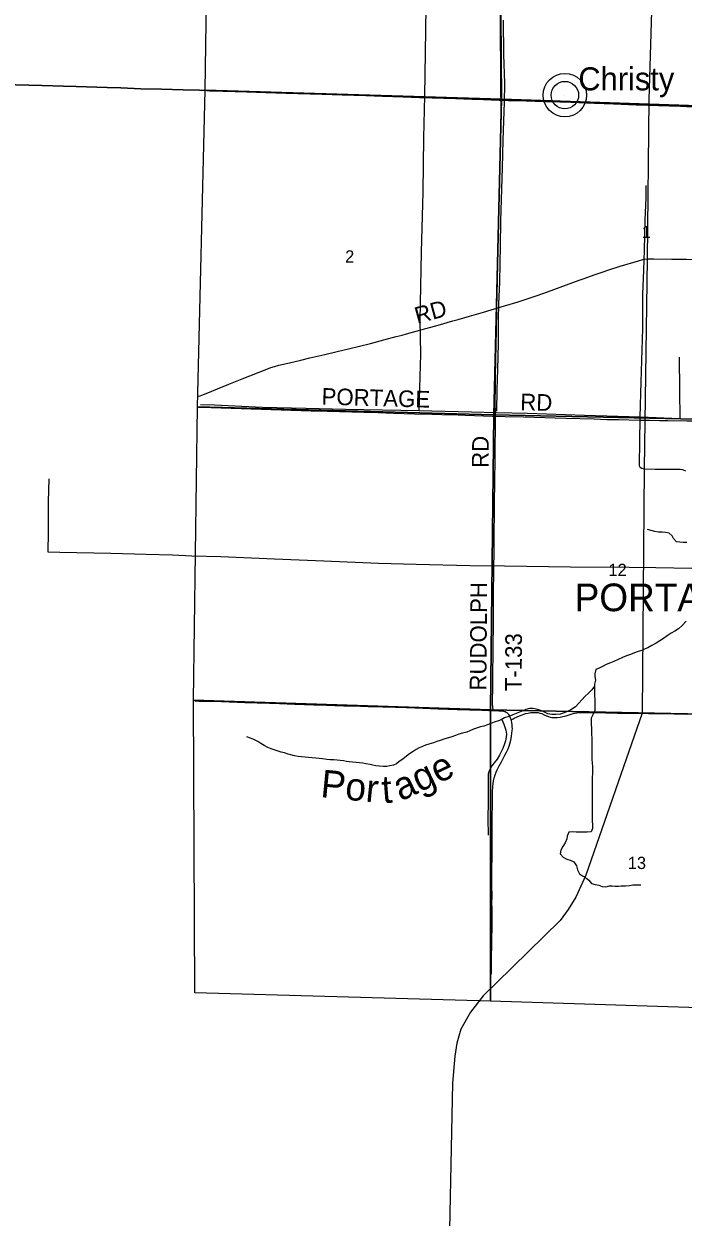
# Model space of a CAD drawing. Extents: x -107 to 120, y -81 to 213.
# Drawn here: x -88.31 to -76.39, y -41 to -19.43 of the extents above; entities that cross this region are included whole.
import ezdxf

# ---------------------------------------------------------------- set-up
doc = ezdxf.new("R2010")
doc.units = 0
for name, color, linetype in [('GM_X_Corporation_Text', 7, 'Continuous'), ('GM_X_Major_River', 7, 'Continuous'), ('GM_X_Major_River_Text', 7, 'Continuous'), ('GM_X_Minor_River', 7, 'Continuous'), ('GM_X_Rail_Line', 7, 'Continuous'), ('GM_X_Section', 7, 'Continuous'), ('GM_X_Section_Text', 7, 'Continuous'), ('GM_X_Township', 7, 'Continuous'), ('GM_X_Township_Road', 7, 'Continuous'), ('GM_X_Township_Road_Text', 7, 'Continuous'), ('GM_X_Unincorporated', 7, 'Continuous'), ('GM_X_Unincorporated_Location', 7, 'Continuous'), ('GM_X_Unincorporated_Text', 7, 'Continuous')]:
    doc.layers.add(name, color=color, linetype=linetype)

msp = doc.modelspace()

# ---------------------------------------------------------------- linework, layer by layer
at = {"layer": 'GM_X_Major_River'}
for points in [[(-76.335, -30.225), (-76.405, -30.307), (-76.474, -30.369), (-76.538, -30.407), (-76.604, -30.447), (-76.676, -30.491), (-76.745, -30.539), (-76.809, -30.583), (-76.875, -30.623), (-76.955, -30.669), (-77.028, -30.707), (-77.078, -30.726), (-77.134, -30.758), (-77.204, -30.778), (-77.27, -30.802), (-77.343, -30.83), (-77.415, -30.854), (-77.485, -30.882), (-77.567, -30.92), (-77.641, -30.955), (-77.704, -30.981), (-77.782, -31.013), (-77.834, -31.039), (-77.898, -31.069)], [(-77.898, -31.069), (-77.966, -31.103), (-77.985, -31.177), (-77.985, -31.227), (-77.975, -31.297), (-77.991, -31.365), (-77.991, -31.402)], [(-77.991, -31.402), (-78.038, -31.47), (-78.108, -31.538), (-78.158, -31.586), (-78.219, -31.648), (-78.273, -31.712), (-78.337, -31.776), (-78.403, -31.821), (-78.468, -31.857), (-78.538, -31.883), (-78.612, -31.909), (-78.692, -31.917), (-78.766, -31.917), (-78.838, -31.904), (-78.906, -31.868), (-78.978, -31.834), (-79.046, -31.816), (-79.099, -31.809), (-79.167, -31.809), (-79.235, -31.825), (-79.289, -31.847), (-79.345, -31.873), (-79.407, -31.897), (-79.468, -31.921), (-79.54, -31.952), (-79.616, -31.978), (-79.68, -32.012), (-79.73, -32.03), (-79.807, -32.054), (-79.863, -32.076), (-79.927, -32.1), (-79.991, -32.124), (-80.053, -32.137), (-80.127, -32.161), (-80.178, -32.181), (-80.244, -32.211), (-80.302, -32.233), (-80.38, -32.255), (-80.446, -32.273), (-80.502, -32.293), (-80.571, -32.316), (-80.631, -32.336), (-80.699, -32.356), (-80.783, -32.388), (-80.841, -32.404), (-80.901, -32.43), (-80.984, -32.454), (-81.046, -32.471), (-81.1, -32.491), (-81.162, -32.519), (-81.214, -32.545), (-81.269, -32.583), (-81.335, -32.629), (-81.389, -32.667), (-81.459, -32.725), (-81.52, -32.767), (-81.572, -32.809), (-81.624, -32.829), (-81.69, -32.846), (-81.748, -32.854), (-81.808, -32.854), (-81.878, -32.848), (-81.946, -32.842), (-81.997, -32.834), (-82.049, -32.821), (-82.123, -32.805), (-82.177, -32.797), (-82.241, -32.789), (-82.297, -32.781), (-82.369, -32.776), (-82.425, -32.772), (-82.475, -32.764), (-82.529, -32.752), (-82.587, -32.744), (-82.643, -32.739), (-82.705, -32.737), (-82.77, -32.735), (-82.832, -32.727), (-82.906, -32.717), (-82.968, -32.708), (-83.03, -32.704), (-83.098, -32.698), (-83.164, -32.692), (-83.22, -32.688), (-83.288, -32.681), (-83.346, -32.675), (-83.416, -32.665), (-83.478, -32.647), (-83.53, -32.63), (-83.596, -32.61), (-83.654, -32.599), (-83.707, -32.58), (-83.763, -32.558), (-83.835, -32.535), (-83.897, -32.511), (-83.965, -32.473), (-84.021, -32.438), (-84.077, -32.406), (-84.149, -32.37), (-84.207, -32.344), (-84.275, -32.321)]]:
    msp.add_lwpolyline(points, dxfattribs=at)
at = {"layer": 'GM_X_Minor_River'}
for points in [[(-81.159, -26.425), (-81.132, -25.4), (-81.14, -24.782), (-81.116, -23.555), (-81.089, -22.464), (-81.074, -21.487), (-81.06, -20.727), (-81.047, -19.954), (-81.035, -19.128), (-81.018, -18.394), (-81.006, -17.654), (-80.999, -17.221), (-81.008, -16.819), (-81.009, -16.529), (-81.002, -16.198), (-81.001, -15.877)], [(-79.645, -19.361), (-79.637, -19.979), (-79.62, -20.502), (-79.625, -20.847), (-79.639, -21.182), (-79.646, -21.531), (-79.659, -22.029), (-79.679, -22.606), (-79.688, -22.993), (-79.697, -23.433), (-79.704, -23.763), (-79.711, -24.098), (-79.725, -24.487), (-79.736, -24.776), (-79.735, -25.209), (-79.748, -25.679), (-79.756, -26.036), (-79.763, -26.433)], [(-76.442, -27.488), (-76.895, -27.484), (-77.088, -27.478), (-77.134, -27.47), (-77.164, -27.447), (-77.178, -27.425), (-77.181, -27.387), (-77.172, -26.988), (-77.169, -26.541), (-77.147, -25.903), (-77.12, -24.938), (-77.116, -24.319), (-77.098, -23.882), (-77.085, -23.521), (-77.074, -22.975), (-77.056, -22.572), (-77.056, -22.347)], [(-76.46, -25.456), (-76.454, -26.052), (-76.448, -26.569), (-77.169, -26.541), (-78.174, -26.506), (-79.202, -26.475), (-79.765, -26.463), (-80.218, -26.447), (-80.935, -26.431), (-81.159, -26.425), (-82.495, -26.402), (-83.212, -26.382), (-83.992, -26.364), (-84.863, -26.319), (-85.113, -26.318)], [(-76.342, -27.516), (-76.393, -27.491), (-76.442, -27.488)], [(-87.858, -27.654), (-87.865, -28.071), (-87.865, -28.619), (-87.872, -28.974), (-87.654, -28.978), (-86.732, -28.995), (-86.095, -29.015), (-85.617, -29.028), (-85.272, -29.045), (-84.749, -29.057), (-83.776, -29.1), (-82.886, -29.135), (-81.897, -29.176), (-81.218, -29.198), (-80.246, -29.221), (-79.621, -29.229), (-78.425, -29.248), (-77.366, -29.254), (-76.881, -29.259), (-76.234, -29.269), (-75.901, -29.28), (-75.604, -29.287)], [(-76.322, -28.804), (-76.391, -28.805), (-76.447, -28.801), (-76.511, -28.791), (-76.561, -28.735), (-76.586, -28.684), (-76.64, -28.636), (-76.708, -28.622), (-76.771, -28.618), (-76.837, -28.618), (-76.901, -28.605), (-76.965, -28.587), (-77.033, -28.567)], [(-77.991, -31.402), (-77.994, -31.506), (-77.992, -31.57), (-77.988, -31.644), (-77.988, -31.704), (-77.987, -31.773), (-77.983, -31.841), (-78.013, -31.909), (-78.051, -31.979), (-78.052, -32.045), (-78.05, -32.097), (-78.048, -32.165), (-78.046, -32.216), (-78.046, -32.268), (-78.041, -32.342), (-78.039, -32.408), (-78.039, -32.544), (-78.039, -32.609), (-78.042, -32.675), (-78.04, -32.725), (-78.036, -32.793), (-78.03, -32.857), (-78.028, -32.926), (-78.029, -32.992), (-78.033, -33.044), (-78.035, -33.102), (-78.035, -33.172), (-78.033, -33.244), (-78.036, -33.315), (-78.034, -33.383), (-78.034, -33.511), (-78.032, -33.577), (-78.031, -33.651), (-78.033, -33.706), (-78.031, -33.772), (-78.031, -33.848), (-78.029, -33.902), (-78.028, -33.974), (-78.05, -34.034), (-78.122, -34.04), (-78.192, -34.042), (-78.258, -34.042), (-78.322, -34.04), (-78.384, -34.038), (-78.455, -34.043), (-78.483, -34.115), (-78.493, -34.166), (-78.521, -34.238), (-78.566, -34.304), (-78.598, -34.37), (-78.61, -34.432), (-78.56, -34.494), (-78.49, -34.529), (-78.43, -34.547), (-78.366, -34.581), (-78.32, -34.653), (-78.3, -34.724), (-78.263, -34.796), (-78.209, -34.834), (-78.155, -34.862), (-78.095, -34.909), (-78.043, -34.971), (-77.977, -34.987), (-77.915, -35), (-77.851, -35.028), (-77.785, -35.034), (-77.722, -35.012), (-77.67, -35.016), (-77.616, -35.018), (-77.56, -35.019), (-77.51, -35.015), (-77.432, -35.011), (-77.358, -35.005), (-77.3, -34.995), (-77.21, -34.994), (-77.153, -34.996)], [(-79.665, -32.004), (-79.628, -32.087), (-79.597, -32.199), (-79.585, -32.269), (-79.589, -32.327), (-79.599, -32.391), (-79.617, -32.446), (-79.648, -32.528), (-79.686, -32.602), (-79.71, -32.648), (-79.753, -32.722), (-79.803, -32.788), (-79.845, -32.844), (-79.895, -32.932), (-79.914, -32.996), (-79.912, -33.179), (-79.913, -33.5), (-79.918, -33.798), (-79.911, -34.097)]]:
    msp.add_lwpolyline(points, dxfattribs=at)
at = {"layer": 'GM_X_Rail_Line'}
msp.add_lwpolyline([(-76.938, -18.389), (-77.01, -20.802), (-77.04, -23.683), (-77.093, -27.462), (-77.13, -31.891), (-78.149, -34.821), (-78.332, -35.218), (-78.47, -35.439), (-78.614, -35.638), (-79.766, -36.764), (-80.006, -37.004), (-80.231, -37.298), (-80.406, -37.602), (-80.479, -37.86), (-80.516, -38.09), (-80.556, -38.584), (-80.636, -42.405)], dxfattribs=at)
at = {"layer": 'GM_X_Section'}
for points in [[(-84.948, -15.325), (-79.714, -15.483), (-79.671, -20.786), (-85.027, -20.624)], [(-79.714, -15.483), (-74.3, -15.65), (-74.292, -15.724), (-74.333, -20.972), (-79.671, -20.786)], [(-85.027, -20.624), (-79.671, -20.786), (-79.814, -26.495), (-85.166, -26.35)], [(-79.671, -20.786), (-74.333, -20.972), (-74.457, -26.613), (-79.814, -26.495)], [(-85.166, -26.35), (-79.814, -26.495), (-79.874, -31.832), (-85.243, -31.655)], [(-79.814, -26.495), (-74.457, -26.613), (-74.459, -26.879), (-74.531, -31.942), (-79.874, -31.832)], [(-85.243, -31.655), (-79.874, -31.832), (-79.873, -37.1), (-85.219, -36.95)], [(-79.874, -31.832), (-74.531, -31.942), (-74.528, -32.154), (-74.587, -37.265), (-79.873, -37.1)]]:
    msp.add_lwpolyline(points, close=True, dxfattribs=at)
at = {"layer": 'GM_X_Township'}
for points in [[(-88.687, -20.521), (-87.982, -20.542), (-87.588, -20.554), (-87.359, -20.561), (-86.801, -20.579), (-86.555, -20.587), (-86.195, -20.6), (-85.818, -20.61), (-85.424, -20.62), (-85.129, -20.628), (-85.002, -20.632), (-84.949, -20.634), (-84.703, -20.643), (-84.276, -20.656), (-83.932, -20.666), (-83.571, -20.677), (-82.915, -20.696), (-82.554, -20.708), (-82.127, -20.722), (-81.832, -20.731), (-81.455, -20.743), (-81.16, -20.753), (-80.931, -20.761), (-80.504, -20.775), (-80.209, -20.785), (-79.996, -20.792), (-79.717, -20.803), (-79.681, -20.804), (-79.553, -20.808), (-79.225, -20.819), (-78.913, -20.828), (-78.618, -20.836), (-78.421, -20.843), (-77.995, -20.858), (-77.651, -20.871), (-77.241, -20.886), (-77.028, -20.895), (-76.832, -20.901), (-76.438, -20.914), (-76.209, -20.922)], [(-76.209, -20.922), (-76.438, -20.914), (-76.832, -20.901), (-77.028, -20.895), (-77.241, -20.886), (-77.651, -20.871), (-77.995, -20.858), (-78.421, -20.843), (-78.618, -20.836), (-78.913, -20.828), (-79.225, -20.819), (-79.553, -20.808), (-79.681, -20.804), (-79.717, -20.803), (-79.996, -20.792), (-80.209, -20.785), (-80.504, -20.775), (-80.931, -20.761), (-81.16, -20.753), (-81.455, -20.743), (-81.832, -20.731), (-82.127, -20.722), (-82.554, -20.708), (-82.915, -20.696), (-83.571, -20.677), (-83.932, -20.666), (-84.276, -20.656), (-84.703, -20.643), (-84.949, -20.634), (-85.002, -20.632), (-85.129, -20.628), (-85.424, -20.62), (-85.818, -20.61), (-86.195, -20.6), (-86.555, -20.587), (-86.801, -20.579), (-87.359, -20.561), (-87.588, -20.554), (-87.982, -20.542), (-88.687, -20.521)]]:
    msp.add_lwpolyline(points, dxfattribs=at)
at = {"layer": 'GM_X_Township_Road'}
msp.add_line((-77.143, -26.593), (-77.108, -26.593), dxfattribs=at)
for points in [[(-79.68, -20.807), (-79.684, -20.71), (-79.687, -20.431), (-79.691, -19.413), (-79.693, -19.019), (-79.696, -18.723), (-79.696, -18.379), (-79.695, -18.321)], [(-85.001, -20.635), (-84.948, -20.637), (-84.701, -20.646), (-84.275, -20.659), (-83.93, -20.669), (-83.57, -20.68), (-82.913, -20.699), (-82.552, -20.711), (-82.126, -20.725), (-81.831, -20.734), (-81.453, -20.746), (-81.158, -20.756), (-81.02, -20.761)], [(-81.02, -20.761), (-80.929, -20.764), (-80.503, -20.778), (-80.208, -20.788), (-79.994, -20.795), (-79.716, -20.806), (-79.68, -20.807)], [(-79.758, -24.568), (-79.754, -24.32), (-79.746, -24.057), (-79.74, -23.762), (-79.733, -23.385), (-79.719, -22.777), (-79.715, -22.613), (-79.709, -22.351), (-79.693, -21.678), (-79.682, -21.235), (-79.677, -21.054), (-79.677, -20.907), (-79.679, -20.825), (-79.68, -20.807)], [(-79.68, -20.807), (-79.552, -20.811), (-79.223, -20.822), (-78.912, -20.831), (-78.617, -20.839), (-78.42, -20.846), (-77.994, -20.861), (-77.649, -20.874), (-77.239, -20.889), (-77.027, -20.898), (-76.831, -20.904), (-76.437, -20.916), (-76.207, -20.925), (-75.994, -20.932), (-75.814, -20.939), (-75.437, -20.955), (-74.896, -20.978), (-74.617, -20.987), (-74.426, -20.996)], [(-79.758, -24.568), (-79.621, -24.528), (-79.37, -24.452), (-79.245, -24.412), (-79.028, -24.337), (-78.842, -24.272), (-78.271, -24.064), (-78.194, -24.038), (-77.978, -23.96), (-77.838, -23.911), (-77.73, -23.874), (-77.526, -23.81), (-77.196, -23.712), (-77.117, -23.689), (-77.085, -23.682), (-77.08, -23.682)], [(-77.08, -23.682), (-77.048, -23.678), (-77.003, -23.675), (-76.921, -23.676), (-76.593, -23.683), (-76.331, -23.685), (-76.166, -23.689), (-76.035, -23.692), (-75.822, -23.696), (-75.363, -23.705), (-75.084, -23.711), (-74.903, -23.714), (-74.405, -23.726)], [(-85.151, -26.162), (-85.12, -26.152), (-85.089, -26.142), (-85.013, -26.113), (-84.603, -25.945), (-84.359, -25.846), (-83.917, -25.67), (-83.84, -25.642), (-83.778, -25.622), (-83.699, -25.6), (-83.507, -25.554), (-83.299, -25.507), (-83.14, -25.469), (-82.868, -25.404), (-82.645, -25.35), (-82.437, -25.301), (-82.039, -25.204), (-81.8, -25.142), (-81.579, -25.082), (-81.468, -25.054), (-81.389, -25.031), (-81.104, -24.955), (-80.819, -24.874), (-80.55, -24.8), (-80.456, -24.773), (-80.251, -24.713), (-79.999, -24.64), (-79.858, -24.597), (-79.758, -24.568)], [(-79.784, -26.519), (-79.786, -26.224), (-79.783, -26.027), (-79.78, -25.814), (-79.776, -25.502), (-79.765, -24.96), (-79.758, -24.599), (-79.758, -24.568)], [(-85.149, -26.359), (-85.099, -26.361), (-83.836, -26.399), (-83.115, -26.423), (-82.82, -26.43), (-82.164, -26.448), (-81.901, -26.455), (-81.623, -26.464), (-81.245, -26.476), (-80.934, -26.485), (-80.753, -26.489), (-80.458, -26.498), (-80.327, -26.502), (-80.163, -26.506), (-79.835, -26.518), (-79.784, -26.519)], [(-79.823, -31.844), (-79.826, -31.822), (-79.829, -31.796), (-79.831, -31.773), (-79.833, -31.74), (-79.833, -31.657), (-79.829, -31.444), (-79.827, -31.132), (-79.825, -30.853), (-79.822, -30.59), (-79.82, -30.377), (-79.818, -30.196), (-79.816, -29.852), (-79.815, -29.655), (-79.813, -29.376), (-79.807, -28.867), (-79.804, -28.588), (-79.8, -28.325), (-79.797, -28.112), (-79.792, -27.685), (-79.787, -27.324), (-79.785, -27.094), (-79.783, -26.717), (-79.784, -26.519)], [(-79.784, -26.519), (-79.606, -26.524), (-79.278, -26.533), (-78.507, -26.557), (-77.999, -26.572), (-77.769, -26.579), (-77.556, -26.584), (-77.179, -26.593), (-77.143, -26.593)], [(-77.108, -26.593), (-76.994, -26.594), (-76.819, -26.597)], [(-76.819, -26.597), (-76.666, -26.6), (-76.321, -26.604), (-76.108, -26.605), (-75.829, -26.609), (-75.763, -26.61), (-75.633, -26.613), (-75.387, -26.619), (-75.174, -26.624), (-75.098, -26.626)], [(-85.218, -31.668), (-85.144, -31.671), (-84.951, -31.676), (-84.737, -31.682), (-84.311, -31.696), (-83.868, -31.71), (-83.688, -31.716), (-83.409, -31.726), (-83.065, -31.739), (-82.835, -31.747), (-82.523, -31.756), (-82.359, -31.761), (-82.08, -31.768), (-81.818, -31.778), (-81.588, -31.785), (-81.392, -31.79), (-81.096, -31.801), (-80.818, -31.811), (-80.473, -31.822), (-80.03, -31.838), (-79.899, -31.843), (-79.823, -31.844)], [(-79.823, -31.844), (-79.784, -31.844), (-79.719, -31.847), (-79.672, -31.85), (-79.637, -31.855), (-79.621, -31.858), (-79.606, -31.863), (-79.591, -31.871), (-79.577, -31.88), (-79.565, -31.891), (-79.555, -31.904), (-79.546, -31.917), (-79.537, -31.932), (-79.522, -31.962), (-79.51, -31.987), (-79.504, -32), (-79.5, -32.011)], [(-79.5, -32.011), (-79.478, -32.001), (-79.459, -31.991), (-79.445, -31.984), (-79.39, -31.957), (-79.345, -31.938), (-79.283, -31.914), (-79.237, -31.9), (-79.189, -31.888), (-79.14, -31.88), (-79.107, -31.877), (-79.075, -31.876), (-79.042, -31.877), (-79.009, -31.881), (-78.977, -31.889), (-78.946, -31.899), (-78.901, -31.919), (-78.857, -31.94), (-78.826, -31.952), (-78.795, -31.961), (-78.762, -31.967), (-78.73, -31.97), (-78.697, -31.971), (-78.664, -31.968), (-78.615, -31.962), (-78.567, -31.953), (-78.503, -31.937), (-78.378, -31.897), (-78.346, -31.889), (-78.314, -31.883), (-78.282, -31.879), (-78.232, -31.877), (-78.134, -31.878), (-77.97, -31.881), (-77.789, -31.885), (-77.576, -31.889), (-77.297, -31.893), (-77.018, -31.898), (-76.805, -31.9), (-76.313, -31.91)], [(-79.854, -36.61), (-79.854, -36.542), (-79.852, -36.264), (-79.849, -36.12), (-79.846, -35.972), (-79.844, -35.759), (-79.843, -35.644), (-79.844, -35.415), (-79.845, -35.333), (-79.844, -35.202), (-79.846, -35.005), (-79.847, -34.857), (-79.847, -34.71), (-79.844, -34.48), (-79.841, -34.201), (-79.839, -33.872), (-79.835, -33.429), (-79.834, -33.314), (-79.829, -33.216), (-79.825, -33.166), (-79.817, -33.117), (-79.806, -33.069), (-79.787, -33.006), (-79.77, -32.959), (-79.752, -32.914), (-79.723, -32.854), (-79.675, -32.768), (-79.611, -32.653), (-79.581, -32.595), (-79.555, -32.535), (-79.537, -32.489), (-79.523, -32.443), (-79.506, -32.38), (-79.494, -32.315), (-79.484, -32.251), (-79.479, -32.202), (-79.477, -32.169), (-79.478, -32.137), (-79.48, -32.105), (-79.488, -32.055), (-79.493, -32.032), (-79.5, -32.011)]]:
    msp.add_lwpolyline(points, dxfattribs=at)
at = {"layer": 'GM_X_Unincorporated'}
for radius in [0.393, 0.249]:
    msp.add_circle((-78.527, -20.716), radius, dxfattribs=at)
at = {"layer": 'GM_X_Unincorporated_Location'}
msp.add_line((-78.527, -20.716), (-78.527, -20.716), dxfattribs=at)

# ---------------------------------------------------------------- texts
at = {"layer": 'GM_X_Corporation_Text'}
msp.add_text('PORTAGE', height=0.5, rotation=0, dxfattribs=at).set_placement((-78.351, -30.047))
at = {"layer": 'GM_X_Major_River_Text'}
for s, height, rotation, p in [('age', 0.5003, 25.323, (-81.492, -33.489)), ('Por', 0.5002, 354.3251, (-82.956, -33.407)), ('t', 0.5, 4.3249, (-81.821, -33.521))]:
    msp.add_text(s, height=height, rotation=rotation, dxfattribs=at).set_placement(p)
at = {"layer": 'GM_X_Section_Text'}
for s, p in [('1', (-77.136, -23.302)), ('2', (-82.499, -23.743)), ('12', (-77.739, -29.41)), ('13', (-77.389, -34.709))]:
    msp.add_text(s, height=0.221, rotation=0, dxfattribs=at).set_placement(p)
at = {"layer": 'GM_X_Township_Road_Text'}
for s, rotation, p in [('RD', 15.2121, (-81.196, -24.854)), ('PORTAGE', 358.3556, (-82.928, -26.311)), ('RD', 358.5194, (-79.337, -26.412)), ('RD', 89.5083, (-79.907, -27.457)), ('RUDOLPH', 89.5669, (-79.947, -31.484)), ('T-133', 89.7192, (-79.308, -31.494))]:
    msp.add_text(s, height=0.3, rotation=rotation, dxfattribs=at).set_placement(p)
at = {"layer": 'GM_X_Unincorporated_Text'}
msp.add_text('Christy', height=0.417, rotation=0, dxfattribs=at).set_placement((-78.284, -20.63))

doc.saveas('drawing.dxf')
